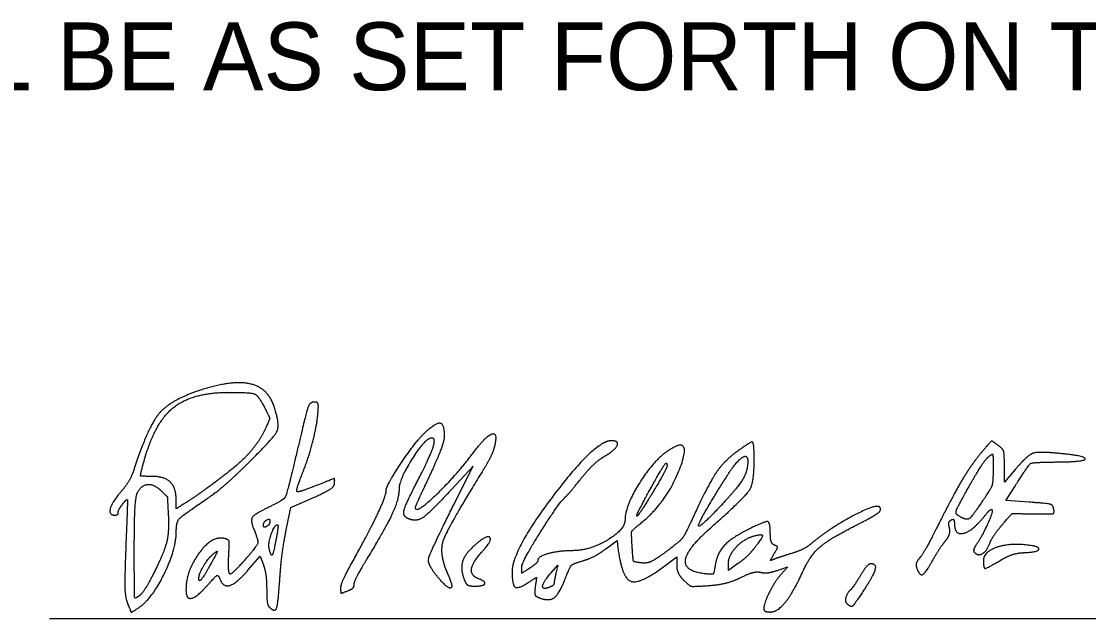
# Model space of a CAD drawing. Extents: x -5.6 to 34, y 0 to 22.
# Drawn here: x 26.258 to 28.462, y 6.99 to 8.223 of the extents above; entities that cross this region are included whole.
import ezdxf

# ---------------------------------------------------------------- set-up
doc = ezdxf.new("R2010")
doc.units = 0
for name, color, linetype in [('Default', 7, 'Continuous'), ('SH_Data', 7, 'Continuous'), ('SH_Text', 7, 'Continuous')]:
    doc.layers.add(name, color=color, linetype=linetype)

msp = doc.modelspace()

# ---------------------------------------------------------------- linework, layer by layer
at = {"layer": 'Default'}
msp.add_line((26.316, 6.9897), (29.764, 6.9897), dxfattribs=at)
at = {"layer": 'SH_Text'}
for p, q in [((26.918, 7.0538), (26.918, 7.0538)), ((27.172, 7.0717), (27.172, 7.0717)), ((27.9629, 7.0207), (27.9629, 7.0207))]:
    msp.add_line(p, q, dxfattribs=at)
for points in [[(27.1505, 7.224), (27.191, 7.3047), (27.1469, 7.2571)], [(28.3101, 7.2974), (28.288, 7.2716), (28.288, 7.3047)], [(28.3393, 7.2301), (28.2908, 7.2334), (28.3099, 7.2634)], [(26.8051, 7.1729), (26.8146, 7.219), (26.8596, 7.2388)], [(27.4647, 7.1336), (27.488, 7.1508), (27.4899, 7.1354)], [(26.7272, 7.091), (26.7509, 7.1187), (26.7578, 7.1006)], [(27.3518, 7.0843), (27.3657, 7.1001), (27.3619, 7.0834)], [(27.5896, 7.1009), (27.6113, 7.1174), (27.6113, 7.1004)], [(27.7377, 7.1032), (27.718, 7.0892), (27.718, 7.1029)], [(27.819, 7.0894), (27.8405, 7.0969), (27.8273, 7.0818)]]:
    msp.add_lwpolyline(points, dxfattribs=at)
for points in [[(26.78, 7.4275), (26.7667, 7.4672), (26.6899, 7.4824), (26.6211, 7.459)], [(26.6211, 7.459), (26.5639, 7.4395), (26.5188, 7.3841), (26.4913, 7.2997)], [(26.5076, 7.3008), (26.5296, 7.3886), (26.6079, 7.4568), (26.6866, 7.4568)], [(26.6866, 7.4568), (26.7326, 7.4568), (26.7476, 7.45), (26.7615, 7.4231)], [(26.7257, 7.31), (26.7801, 7.3635), (26.7924, 7.3902), (26.78, 7.4275)], [(26.8629, 7.4368), (26.8538, 7.4368), (26.8459, 7.4142), (26.8277, 7.3368)], [(26.8405, 7.2947), (26.8541, 7.3294), (26.8713, 7.4044), (26.8713, 7.429)], [(26.8713, 7.429), (26.8713, 7.4332), (26.8675, 7.4368), (26.8629, 7.4368)], [(26.7615, 7.4231), (26.7709, 7.4048), (26.7708, 7.401), (26.7601, 7.3783)], [(27.0904, 7.3726), (27.1136, 7.3948), (27.1313, 7.3923), (27.1313, 7.3669)], [(26.7601, 7.3783), (26.7467, 7.3499), (26.6985, 7.3005), (26.6487, 7.2644)], [(27.0113, 7.2542), (27.0113, 7.2645), (27.0714, 7.3545), (27.0904, 7.3726)], [(27.1023, 7.3617), (27.0884, 7.3575), (27.038, 7.276), (27.038, 7.2578)], [(27.0757, 7.273), (27.1028, 7.3253), (27.1149, 7.3656), (27.1023, 7.3617)], [(27.1313, 7.3669), (27.1313, 7.3575), (27.1178, 7.321), (27.1013, 7.2857)], [(27.1933, 7.3346), (27.2186, 7.3682), (27.2421, 7.3741), (27.2349, 7.3451)], [(27.2349, 7.3451), (27.2324, 7.335), (27.222, 7.3133), (27.2118, 7.2968)], [(27.4759, 7.3568), (27.4424, 7.3568), (27.2713, 7.131), (27.2713, 7.0869)], [(27.4625, 7.325), (27.4846, 7.338), (27.4925, 7.3568), (27.4759, 7.3568)], [(27.5343, 7.1843), (27.5911, 7.229), (27.6453, 7.3726), (27.591, 7.3346)], [(27.7713, 7.3188), (27.7713, 7.3531), (27.7641, 7.3554), (27.7315, 7.3313)], [(28.2746, 7.3477), (28.2623, 7.3568), (28.2599, 7.3558), (28.2427, 7.3355)], [(28.288, 7.3047), (28.288, 7.3301), (28.2849, 7.3401), (28.2746, 7.3477)], [(26.8277, 7.3368), (26.8069, 7.2483), (26.8002, 7.2348), (26.7705, 7.2205)], [(27.0713, 7.2191), (27.0713, 7.2044), (27.1549, 7.2836), (27.1933, 7.3346)], [(27.4142, 7.2794), (27.4286, 7.2973), (27.4504, 7.3178), (27.4625, 7.325)], [(27.591, 7.3346), (27.5619, 7.3142), (27.5046, 7.2211), (27.5046, 7.1941)], [(27.7315, 7.3313), (27.7076, 7.3136), (27.6748, 7.2636), (27.6456, 7.2001)], [(27.6786, 7.1745), (27.7522, 7.2403), (27.7713, 7.2699), (27.7713, 7.3188)], [(27.7142, 7.2827), (27.733, 7.3125), (27.758, 7.3306), (27.758, 7.3144)], [(28.2427, 7.3355), (28.22, 7.3085), (28.1813, 7.2435), (28.148, 7.1768)], [(28.2143, 7.2614), (28.2309, 7.2908), (28.249, 7.3187), (28.2545, 7.3233)], [(28.2545, 7.3233), (28.2633, 7.3306), (28.2646, 7.3274), (28.2646, 7.2983)], [(28.4063, 7.3302), (28.3587, 7.3351), (28.3356, 7.3272), (28.3101, 7.2974)], [(28.3986, 7.3131), (28.4522, 7.3135), (28.4575, 7.325), (28.4063, 7.3302)], [(26.4913, 7.2997), (26.4866, 7.2852), (26.4742, 7.2636), (26.4637, 7.2515)], [(26.5268, 7.2834), (26.5047, 7.2834), (26.5035, 7.2845), (26.5076, 7.3008)], [(26.6413, 7.2372), (26.6596, 7.2496), (26.6976, 7.2823), (26.7257, 7.31)], [(27.2118, 7.2968), (27.1377, 7.1773), (27.1196, 7.1232), (27.1391, 7.0804)], [(27.5511, 7.2468), (27.5779, 7.2955), (27.5913, 7.3153), (27.5913, 7.3062)], [(27.5913, 7.3062), (27.5913, 7.3024), (27.5806, 7.2815), (27.5675, 7.2597)], [(27.758, 7.3144), (27.758, 7.2964), (27.7412, 7.2653), (27.7176, 7.2394)], [(28.2646, 7.2983), (28.2646, 7.2717), (28.2602, 7.2583), (28.243, 7.2326)], [(28.3099, 7.2634), (28.3384, 7.3082), (28.3464, 7.3126), (28.3986, 7.3131)], [(26.578, 7.2324), (26.578, 7.2593), (26.5537, 7.2834), (26.5268, 7.2834)], [(26.8271, 7.252), (26.8258, 7.2534), (26.8318, 7.2726), (26.8405, 7.2947)], [(26.9046, 7.2677), (26.9046, 7.2792), (26.9048, 7.2793), (26.864, 7.2632)], [(27.0596, 7.1949), (27.0454, 7.2), (27.0503, 7.224), (27.0757, 7.273)], [(27.1013, 7.2857), (27.0848, 7.2504), (27.0713, 7.2204), (27.0713, 7.2191)], [(27.384, 7.2434), (27.3862, 7.2453), (27.3998, 7.2614), (27.4142, 7.2794)], [(27.7176, 7.2394), (27.6571, 7.1731), (27.6558, 7.1902), (27.7142, 7.2827)], [(26.4637, 7.2515), (26.445, 7.23), (26.4381, 7.2034), (26.4513, 7.2034)], [(26.4982, 7.2505), (26.5066, 7.2661), (26.533, 7.2674), (26.5475, 7.2529)], [(26.5475, 7.2529), (26.5597, 7.2407), (26.5593, 7.2422), (26.5615, 7.2034)], [(26.6487, 7.2644), (26.63, 7.2508), (26.6064, 7.2344), (26.5963, 7.2281)], [(26.864, 7.2632), (26.8451, 7.2557), (26.8285, 7.2507), (26.8271, 7.252)], [(26.8596, 7.2388), (26.8844, 7.2498), (26.9046, 7.2628), (26.9046, 7.2677)], [(26.9391, 7.1021), (26.9755, 7.1674), (27.0113, 7.2427), (27.0113, 7.2542)], [(27.038, 7.2578), (27.038, 7.2369), (27.011, 7.178), (26.9723, 7.1143)], [(27.1469, 7.2571), (27.1024, 7.209), (27.0749, 7.1894), (27.0596, 7.1949)], [(27.5675, 7.2597), (27.5354, 7.2062), (27.5238, 7.197), (27.5511, 7.2468)], [(28.1927, 7.2023), (28.1862, 7.2065), (28.1914, 7.2207), (28.2143, 7.2614)], [(26.4679, 7.2271), (26.4768, 7.2387), (26.4774, 7.2295), (26.4738, 7.1401)], [(26.4913, 7.133), (26.4913, 7.1924), (26.4943, 7.2432), (26.4982, 7.2505)], [(26.578, 7.1706), (26.578, 7.1895), (26.5913, 7.2035), (26.6413, 7.2372)], [(26.5963, 7.2281), (26.5782, 7.2166), (26.578, 7.2166), (26.578, 7.2324)], [(27.2913, 7.0964), (27.2913, 7.1072), (27.3696, 7.2313), (27.384, 7.2434)], [(28.243, 7.2326), (28.2211, 7.1999), (28.2084, 7.1922), (28.1927, 7.2023)], [(28.3899, 7.2161), (28.3883, 7.2243), (28.3767, 7.2275), (28.3393, 7.2301)], [(26.4513, 7.2034), (26.455, 7.2034), (26.458, 7.2058), (26.458, 7.2088)], [(26.458, 7.2088), (26.458, 7.2118), (26.4624, 7.22), (26.4679, 7.2271)], [(26.7705, 7.2205), (26.7397, 7.2056), (26.7307, 7.1924), (26.7383, 7.1734)], [(27.12, 7.073), (27.0963, 7.1005), (27.1015, 7.1263), (27.1505, 7.224)], [(28.0304, 7.2199), (28.023, 7.2273), (27.9235, 7.174), (27.888, 7.1437)], [(27.9746, 7.1788), (28.0162, 7.1999), (28.0359, 7.2144), (28.0304, 7.2199)], [(28.2621, 7.2148), (28.2651, 7.2118), (28.2418, 7.1594), (28.2297, 7.1421)], [(28.2469, 7.2015), (28.2538, 7.2103), (28.2607, 7.2163), (28.2621, 7.2148)], [(28.3476, 7.2061), (28.3847, 7.2056), (28.3916, 7.2072), (28.3899, 7.2161)], [(26.5615, 7.2034), (26.5634, 7.1677), (26.5523, 7.1247), (26.5292, 7.0792)], [(26.758, 7.1826), (26.758, 7.1863), (26.761, 7.1912), (26.7646, 7.1934)], [(26.7646, 7.1934), (26.7683, 7.1957), (26.7713, 7.1945), (26.7713, 7.1909)], [(26.7713, 7.1909), (26.7713, 7.1872), (26.7683, 7.1824), (26.7646, 7.1801)], [(27.5046, 7.1941), (27.5046, 7.1734), (27.4317, 7.1301), (27.3966, 7.13)], [(27.6456, 7.2001), (27.6285, 7.1629), (27.6171, 7.1483), (27.5898, 7.1281)], [(27.8046, 7.1634), (27.8046, 7.189), (27.7937, 7.1911), (27.7567, 7.1726)], [(28.1745, 7.1772), (28.1724, 7.1837), (28.1739, 7.1909), (28.1777, 7.1933)], [(28.1777, 7.1933), (28.1815, 7.1956), (28.1846, 7.1928), (28.1846, 7.1869)], [(28.1846, 7.1869), (28.1846, 7.1615), (28.2224, 7.1704), (28.2469, 7.2015)], [(28.2834, 7.1834), (28.3025, 7.2059), (28.3048, 7.2067), (28.3476, 7.2061)], [(26.4998, 7.0118), (26.5277, 7.0304), (26.578, 7.1324), (26.578, 7.1706)], [(26.7383, 7.1734), (26.7477, 7.1501), (26.7452, 7.1406), (26.723, 7.115)], [(26.7646, 7.1801), (26.761, 7.1778), (26.758, 7.179), (26.758, 7.1826)], [(26.7697, 7.1346), (26.7673, 7.1452), (26.781, 7.1834), (26.7872, 7.1834)], [(26.7872, 7.1834), (26.7885, 7.1834), (26.7873, 7.1713), (26.7846, 7.1565)], [(26.7917, 7.0706), (26.7938, 7.1015), (26.7998, 7.1475), (26.8051, 7.1729)], [(27.5193, 7.1388), (27.5175, 7.1666), (27.5195, 7.1727), (27.5343, 7.1843)], [(27.6713, 7.082), (27.6274, 7.0869), (27.6309, 7.1319), (27.6786, 7.1745)], [(27.7567, 7.1726), (27.7225, 7.1554), (27.6938, 7.1228), (27.6902, 7.0968)], [(27.7696, 7.16), (27.7883, 7.1654), (27.7887, 7.1571), (27.771, 7.1346)], [(27.813, 7.1415), (27.8084, 7.1432), (27.8046, 7.153), (27.8046, 7.1634)], [(27.8723, 7.0881), (27.8865, 7.1196), (27.9248, 7.1535), (27.9746, 7.1788)], [(28.148, 7.1768), (28.1344, 7.1493), (28.1186, 7.1216), (28.1131, 7.1153)], [(28.1655, 7.1493), (28.1725, 7.1582), (28.1765, 7.1708), (28.1745, 7.1772)], [(28.2575, 7.1449), (28.2608, 7.1533), (28.2725, 7.1706), (28.2834, 7.1834)], [(26.6756, 7.1555), (26.651, 7.1605), (26.598, 7.0879), (26.598, 7.0492)], [(26.6864, 7.1215), (26.6877, 7.1475), (26.6858, 7.1534), (26.6756, 7.1555)], [(26.7846, 7.1565), (26.7789, 7.1251), (26.7736, 7.1174), (26.7697, 7.1346)], [(27.1954, 7.1422), (27.1746, 7.124), (27.1642, 7.0927), (27.172, 7.0717)], [(27.2084, 7.1266), (27.2309, 7.1508), (27.2201, 7.1637), (27.1954, 7.1422)], [(27.718, 7.1029), (27.718, 7.1196), (27.7492, 7.1541), (27.7696, 7.16)], [(27.8125, 7.1236), (27.8195, 7.1354), (27.8196, 7.1391), (27.813, 7.1415)], [(27.888, 7.1437), (27.8806, 7.1375), (27.8626, 7.1286), (27.848, 7.1241)], [(28.14, 7.1104), (28.147, 7.1229), (28.1585, 7.1404), (28.1655, 7.1493)], [(28.2297, 7.1421), (28.2253, 7.1358), (28.2238, 7.1287), (28.2263, 7.1262)], [(28.2263, 7.1262), (28.2339, 7.1186), (28.2512, 7.129), (28.2575, 7.1449)], [(28.3285, 7.1422), (28.293, 7.1451), (28.2446, 7.1263), (28.2446, 7.1095)], [(28.3273, 7.1259), (28.3589, 7.1271), (28.3598, 7.1397), (28.3285, 7.1422)], [(26.4738, 7.1401), (26.4712, 7.0727), (26.4723, 7.0339), (26.4774, 7.021)], [(26.5018, 7.0372), (26.4923, 7.0293), (26.4913, 7.0385), (26.4913, 7.133)], [(26.6246, 7.0724), (26.6246, 7.0819), (26.6438, 7.1144), (26.6548, 7.1236)], [(26.6548, 7.1236), (26.6632, 7.1305), (26.6623, 7.1262), (26.6513, 7.1064)], [(26.723, 7.115), (26.6934, 7.0809), (26.6843, 7.0825), (26.6864, 7.1215)], [(27.2013, 7.0725), (27.1858, 7.0784), (27.1895, 7.1062), (27.2084, 7.1266)], [(27.3966, 7.13), (27.3691, 7.13), (27.3246, 7.118), (27.3246, 7.1105)], [(27.417, 7.109), (27.4305, 7.113), (27.452, 7.1241), (27.4647, 7.1336)], [(27.4899, 7.1354), (27.498, 7.0733), (27.536, 7.0601), (27.5896, 7.1009)], [(27.5384, 7.1048), (27.523, 7.1065), (27.5211, 7.11), (27.5193, 7.1388)], [(27.5898, 7.1281), (27.5668, 7.1112), (27.5498, 7.1034), (27.5384, 7.1048)], [(27.771, 7.1346), (27.7635, 7.125), (27.7485, 7.1109), (27.7377, 7.1032)], [(27.8125, 7.1123), (27.8051, 7.1092), (27.8051, 7.1112), (27.8125, 7.1236)], [(27.848, 7.1241), (27.8333, 7.1196), (27.8173, 7.1143), (27.8125, 7.1123)], [(28.2812, 7.1109), (28.2943, 7.1187), (28.3151, 7.1254), (28.3273, 7.1259)], [(26.6513, 7.1064), (26.6358, 7.0784), (26.6246, 7.0642), (26.6246, 7.0724)], [(26.7578, 7.1006), (26.7615, 7.0907), (26.7646, 7.0682), (26.7646, 7.0508)], [(26.918, 7.0538), (26.918, 7.0595), (26.9275, 7.0812), (26.9391, 7.1021)], [(26.9723, 7.1143), (26.9571, 7.0892), (26.9446, 7.0649), (26.9446, 7.0601)], [(27.3246, 7.1105), (27.3246, 7.1075), (27.3171, 7.1), (27.308, 7.094)], [(27.3811, 7.0721), (27.3905, 7.0966), (27.3966, 7.1029), (27.417, 7.109)], [(27.6113, 7.1004), (27.6113, 7.0911), (27.6176, 7.0771), (27.6254, 7.0693)], [(27.6902, 7.0968), (27.6884, 7.0834), (27.6846, 7.0805), (27.6713, 7.082)], [(27.9905, 7.0784), (27.9989, 7.0922), (28.0085, 7.1034), (28.0118, 7.1034)], [(28.0118, 7.1034), (28.0241, 7.1034), (28.0175, 7.0784), (27.9973, 7.0479)], [(28.1131, 7.1153), (28.1076, 7.1091), (28.1049, 7.0991), (28.1072, 7.0931)], [(28.1072, 7.0931), (28.1131, 7.0777), (28.1254, 7.0841), (28.14, 7.1104)], [(28.2446, 7.1095), (28.2446, 7.0932), (28.2516, 7.0934), (28.2812, 7.1109)], [(26.5292, 7.0792), (26.5199, 7.0609), (26.5076, 7.042), (26.5018, 7.0372)], [(26.6434, 7.0597), (26.6583, 7.0766), (26.6645, 7.0801), (26.6672, 7.073)], [(26.6672, 7.073), (26.6745, 7.054), (26.7028, 7.0624), (26.7272, 7.091)], [(27.1391, 7.0804), (27.1506, 7.0551), (27.1392, 7.0506), (27.12, 7.073)], [(27.2713, 7.0869), (27.2713, 7.0586), (27.2844, 7.0507), (27.3068, 7.0654)], [(27.308, 7.094), (27.2921, 7.0836), (27.2913, 7.0838), (27.2913, 7.0964)], [(27.3068, 7.0654), (27.3217, 7.0751), (27.3221, 7.0749), (27.3193, 7.0562)], [(27.348, 7.0543), (27.3334, 7.0487), (27.3356, 7.0659), (27.3518, 7.0843)], [(27.3619, 7.0834), (27.3598, 7.0743), (27.3581, 7.0648), (27.3581, 7.0625)], [(27.6774, 7.058), (27.6983, 7.0595), (27.7281, 7.067), (27.7436, 7.0747)], [(27.7436, 7.0747), (27.7592, 7.0824), (27.7776, 7.0872), (27.7847, 7.0853)], [(27.7847, 7.0853), (27.7918, 7.0835), (27.8072, 7.0853), (27.819, 7.0894)], [(27.8273, 7.0818), (27.8138, 7.0664), (27.7913, 7.0214), (27.7913, 7.0099)], [(27.8046, 7.0034), (27.8196, 7.0034), (27.8527, 7.0448), (27.8723, 7.0881)], [(27.9712, 7.0501), (27.9735, 7.0519), (27.9822, 7.0647), (27.9905, 7.0784)], [(26.598, 7.0492), (26.598, 7.0291), (26.6212, 7.0344), (26.6434, 7.0597)], [(26.7692, 7.0144), (26.7814, 7.0022), (26.7883, 7.0194), (26.7917, 7.0706)], [(26.9341, 7.0475), (26.9191, 7.0417), (26.918, 7.0422), (26.918, 7.0538)], [(26.9446, 7.0601), (26.9446, 7.0554), (26.9399, 7.0497), (26.9341, 7.0475)], [(27.172, 7.0717), (27.1757, 7.0616), (27.183, 7.0568), (27.1944, 7.0568)], [(27.1944, 7.0568), (27.2129, 7.0568), (27.2172, 7.0664), (27.2013, 7.0725)], [(27.3193, 7.0562), (27.3173, 7.0425), (27.3197, 7.0357), (27.3277, 7.0326)], [(27.3277, 7.0326), (27.3475, 7.025), (27.3693, 7.0411), (27.3811, 7.0721)], [(27.3581, 7.0625), (27.358, 7.0601), (27.3535, 7.0565), (27.348, 7.0543)], [(27.6254, 7.0693), (27.6372, 7.0575), (27.6455, 7.0557), (27.6774, 7.058)], [(26.7646, 7.0508), (26.7646, 7.0333), (26.7667, 7.0169), (26.7692, 7.0144)], [(27.9629, 7.0207), (27.9586, 7.025), (27.9642, 7.0445), (27.9712, 7.0501)], [(27.9973, 7.0479), (27.9772, 7.0175), (27.971, 7.0126), (27.9629, 7.0207)], [(26.4774, 7.021), (26.4844, 7.0031), (26.4857, 7.0025), (26.4998, 7.0118)], [(27.7913, 7.0099), (27.7913, 7.0063), (27.7973, 7.0034), (27.8046, 7.0034)]]:
    msp.add_open_spline(points, degree=2, dxfattribs=at)

# ---------------------------------------------------------------- texts
at = {"layer": 'SH_Data'}
msp.add_text('TRAFFIC WILL BE AS SET FORTH ON THE PLANS AND ESTIMATES.', height=0.14, dxfattribs=at).set_placement((25, 8.0805))

doc.saveas('drawing.dxf')
